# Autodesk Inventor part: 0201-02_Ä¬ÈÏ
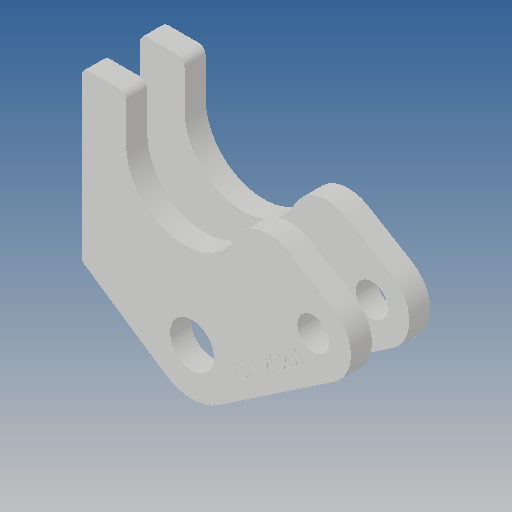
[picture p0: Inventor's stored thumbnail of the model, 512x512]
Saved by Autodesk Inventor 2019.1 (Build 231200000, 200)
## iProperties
Created: 2010-06
Part Number: 0201-02_Ä¬ÈÏ
Material: Ogólny
Document SubType Name: Modeling
Designer: CADENGINEERING4
Density: 1 g/cm^3
Appearance: Domyślna
Author: CADENGINEERING4
Revision Number: ÈÎºÎ
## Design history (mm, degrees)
feature "NONE"
feature "NONE:1"
node "Bryła1"
node "Bryła2"
